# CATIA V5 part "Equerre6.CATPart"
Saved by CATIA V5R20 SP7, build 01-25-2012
Part number: Equerre6
Bounding box of the stored display mesh (mm): x 10 to 20, y 4.049 to 52.992, z 105 to 142.164
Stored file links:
  J:\ACHTUNG2\Equerre6.CATPart
  J:\ACHTUNG2\cmilovidof.CATProduct
  J:\ACHTUNG\IAO non optimisé fini et qui marche à rendre\Bielle4.CATPart
  C:\Users\Cedric\Desktop\ifma\Fichier S3\IAO\Squelette projet IAO\skl_general2.CATPart
  J:\ACHTUNG\IAO non optimisé fini et qui marche à rendre\Equerre6.CATPart
  J:\ACHTUNG2\Patin3.CATPart
  J:\ACHTUNG2\skl_Equerre6.CATPart
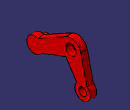
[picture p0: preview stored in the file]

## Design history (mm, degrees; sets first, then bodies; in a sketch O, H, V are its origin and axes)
Parameters
  LENGTH = 64 mm
External parameters (linked from other documents)
  External.diam_roue = 64 mm
  External.diam_roue.1 = 64 mm
Set1
  Plane1: linked copy from another document
  Line1 "Axe_Equerre6Socle": linked copy from another document
  Line2 "Axe_Equerre6Patin2": linked copy from another document
  Line3 "Axe_Equerre6Bielle4": linked copy from another document
  Line4: linked copy from another document
  Line5: linked copy from another document
Body1 (main body)
  Sketch1 on Plane1, origin (15, 0, 0), H (0, 1, 0), V (0, 0, 1)
    point P1 (34.2535, 127.866)
    point P2 (34.2535, 127.866)
    construction circle A1 centre (47, 111) radius 6
    arc A2 centre (38.0408, 134.3395) radius 7.861 from (45.694, 136.135) to (34.2276, 141.2137) ccw
    line L1 (12.3961, 129.1037) -> (34.2276, 141.2137)
    line L2 (42.4593, 114.922) -> (34.2535, 127.866)
    point P6 (34.2535, 127.866)
    construction line L3 (38.0408, 134.3395) -> (34.2535, 127.866)
    construction circle A3 centre (10.0334, 123.5885) radius 6
    line L4 (50.4371, 115.9179) -> (45.694, 136.135)
    arc A4 centre (47, 111) radius 6 from (42.4593, 114.922) to (50.4371, 115.9179) ccw
    line L5 (34.2535, 127.866) -> (15.2773, 120.6728)
    arc A5 centre (10.0334, 123.5885) radius 6 from (12.3961, 129.1037) to (15.2773, 120.6728) ccw
    reference projected point E1 (47, 111) from Line2
    circle A6 centre (47, 111) radius 3
    circle A7 centre (38.0408, 134.3395) radius 4
    reference projected point E2 (38.0408, 134.3395) from Line4
    reference projected point E3 (10.0334, 123.5885) from Line5
    radius A1 = 6
    radius A2 = 7.861 {= 7.861*External.diam_roue /64}
    length L3 = 7.5 {= LENGTH *7.5mm/64mm}
    radius A6 = 3 {= 3*External.diam_roue /64}
    radius A5 = 6 {= 6*External.diam_roue /64}
    radius A7 = 4 {= 4*External.diam_roue /64}
    radius A4 = 6 {= 6*External.diam_roue.1 /64}
    coincidence: P2 P1, P6 L2, L3 P2
    tangency: A2 L1, L4 A2
    concentricity: A1 E1, A7 E2, E3 A5
  Pad1: profile Sketch1, direction (1, 0, 0), length 5
  Sketch2 on start face of Pad1, origin (15, 0, 0), H (0, -1, 0), V (0, 0, 1)
    circle A1 centre (-10.0334, 123.5885) radius 3
    reference projected point E1 (-10.0334, 123.5885) from Line5
    radius A1 = 3 {= 3*External.diam_roue /64}
    concentricity: A1 E1
  Pad2: profile Sketch2, direction (-1, 0, 0), length 5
